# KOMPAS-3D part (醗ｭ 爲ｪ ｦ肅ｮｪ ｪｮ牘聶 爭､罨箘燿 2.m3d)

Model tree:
1. Эскиз:1
2. Операция выдавливания:1
     Расстояние 1 = 31
3. Эскиз:16
4. Операция выдавливания:8
     Расстояние 1 = 2; Расстояние 2 = 2
5. Эскиз:17
6. Вырезать элемент выдавливания:12
     Расстояние 1 = 6
7. Эскиз:18
8. Вырезать элемент выдавливания:13
     Расстояние 1 = 5
9. Эскиз:19
10. Вырезать элемент выдавливания:14
     Расстояние 1 = 6
11. Фаска:1
     Угол = 45; Длина 1 = 0.8; Длина 2 = 0.8
12. Фаска:2
     Угол = 45; Длина 1 = 0.8; Длина 2 = 0.8
13. Эскиз:20
14. Вырезать элемент выдавливания:15
     Расстояние 1 = 24
15. Фаска:4
     Угол = 45; Длина 1 = 0.5; Длина 2 = 0.5
16. Фаска:5
     Угол = 45; Длина 1 = 0.5; Длина 2 = 0.5
17. Эскиз:21
18. Эскиз:22
19. Вырезать элемент выдавливания:16
     Расстояние 1 = 24
20. Операция выдавливания:10
     Толщина стенки 1 = 0.4; Расстояние 1 = 10; Расстояние 2 = 23.1
21. Эскиз:24
22. Вырезать элемент выдавливания:18
     Расстояние 1 = 8
23. Фаска:7
     Угол = 45; Длина 1 = 0.2; Длина 2 = 0.2
24. Эскиз:25
25. Вырезать элемент выдавливания:19
     Расстояние 1 = 8
26. Операция выдавливания:11
     Толщина стенки 1 = 0.4; Расстояние 1 = 10; Расстояние 2 = 5; На расстояние 2 = 5
27. Зеркальный массив:2  (with: Операция выдавливания:8, Фаска:4, Вырезать элемент выдавливания:19)  (labels: Экземпляр ( 1 ); Экземпляр ( 2 ))
28. Эскиз:27
29. Вырезать элемент выдавливания:23
     Расстояние 1 = 1.1
30. Фаска:11
     Угол = 45; Длина 1 = 1; Длина 2 = 1
31. Фаска:12
     Угол = 45; Длина 1 = 0.5; Длина 2 = 0.5

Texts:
  Экземпляр ( 1 )
  Экземпляр ( 2 )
